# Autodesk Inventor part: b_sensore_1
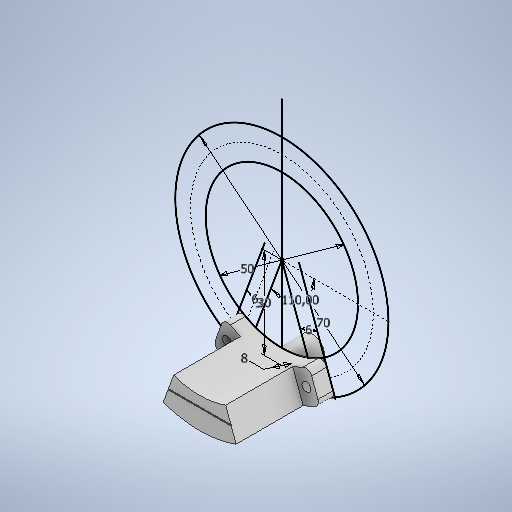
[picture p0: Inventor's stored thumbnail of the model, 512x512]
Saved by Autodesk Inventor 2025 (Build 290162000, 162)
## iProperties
Created: 2026-03
Part Number: b_sensore_1
Material: Generico
Document SubType Name: Modeling
Designer: Ryzen5700u
Density: 1 g/cm^3
Appearance: Default
Author: Ryzen5700u
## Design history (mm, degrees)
sketch "Schizzo1" dims "d0" = 70
  geometry: L1 (0, 0)-(-11.971, -32.889); L2 (0, 0)-(35, 0); L3 (0, 0)-(0, 45.813); L4 (0, 0)-(11.971, -32.889); L5 (-5.638, 2.052)-(-17.609, -30.837); L6 (5.615, 2.115)-(17.586, -30.775); L7 (0, 0)-(0, -30); L8 (-2.819, 1.026)-(-14.79, -31.863); C1 r 25 at (0, 0); C2 r 4 at (0, -30); A1 r 30 centre (0, 0) between (0, -30) and (-13.028, -27.023); 10 further points
  constraints: 16 end point, 4 coincident, 3 centre point, 3 parallel, 2 point on circle, 2 symmetric about line, 2 vertical, 1 equal length, 1 horizontal, 1 point on line, 3 other
  dimensions: "d1" = 50 diameter of C1; "d2" = 110 deg angle of L1 L2; "d5" = 6 distance between parallel lines of L1 L5; "d6" = 6 distance between parallel lines of L4 L6; "d10" = 30 distance of L1.start L7.end; "d11" = 8 diameter of C2; "d17" = 3 distance between parallel lines of L1 L8
extrude "Estrusione1" new body sketch "Schizzo1" distance "d3" = 27; taper "d4" = 0 deg
extrude "Estrusione2" join sketch "Schizzo1" distance "d7" = 5; taper "d8" = 0 deg
fillet "Raccordo1" dims "d9" = 2
extrude "Estrusione3" join sketch "Schizzo1" distance "d12" = 10; taper "d13" = 0 deg
sketch "Schizzo2"
  geometry: L1 (-8.551, -23.492)-(-11.971, -32.889) reference; L2 (-10.261, -28.191)-(10.261, -28.191); L3 (11.971, -32.889)-(8.551, -23.492) reference; L4 (-10.406, -28.591)-(10.406, -28.591); L5 (-8.551, -23.492)-(-11.971, -32.889) reference; L6 (11.971, -32.889)-(8.551, -23.492) reference; A1 r 25 centre (0, 0) between (-8.551, -23.492) and (8.551, -23.492) reference; A2 r 35 centre (0, 0) between (-11.971, -32.889) and (11.971, -32.889) reference; 3 further points
  constraints: 4 end point, 2 midpoint, 2 point on line, 1 parallel
  dimensions: "d14" = 0.4 distance between parallel lines of L2 L4
extrude "Estrusione4" cut sketch "Schizzo2" distance "d15" = 0.2; taper "d16" = 0 deg
hole "Foro1" sketch "Schizzo1" diameter "d18" = 2.9; stored, may be unused: countersink angle "d22" = 90 deg, drill point angle "d24" = 118 deg; dims "d19" = 6, "d20" = 5.5, "d21" = 2.9, "d23" = 8
node "Solido1"
node "Linea chiusa proiettata1"
